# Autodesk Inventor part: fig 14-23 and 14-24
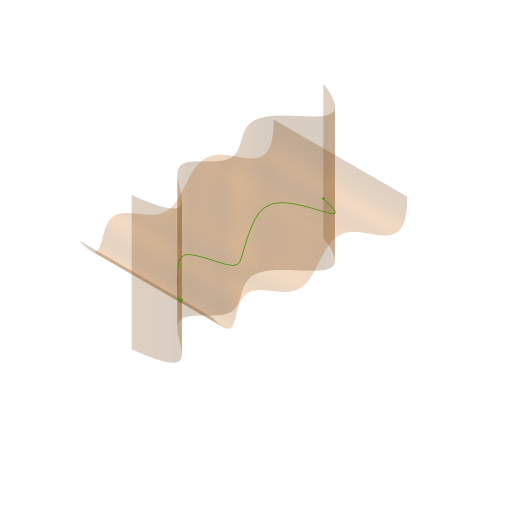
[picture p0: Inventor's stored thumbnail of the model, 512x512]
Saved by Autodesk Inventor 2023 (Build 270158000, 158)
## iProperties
Created: 2007-05
Part Number: fig 14-23 and 14-24
Document SubType Name: Modeling
Designer: Administrator
Density: 1 g/cm^3
Material: Generic
Appearance: Default
Author: Administrator
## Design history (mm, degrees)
node "Sketch1"
node "Sketch2"
sketch "Sketch3"
  geometry: 7 further points
  constraints: 7 other
extrude_surface "ExtrusionSrf1" sketch "Sketch3" dims "d0" = 50, "d1" = 0
sketch "Sketch4"
  geometry: 7 further points
  constraints: 7 other
extrude_surface "ExtrusionSrf2" sketch "Sketch4" dims "d2" = 50, "d3" = 0
sketch "3D Sketch1"
  node "3D Intersection1"
body "Srf1"
body "Srf2"
